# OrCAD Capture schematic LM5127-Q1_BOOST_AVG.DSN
size Custom; title: LM5127-Q1 2.2MHz Wide VIN Automotive Front-stage; rev: 1.0; note: Datasheet: NA     EVM: NA; note: Synchronous Step Down Converter
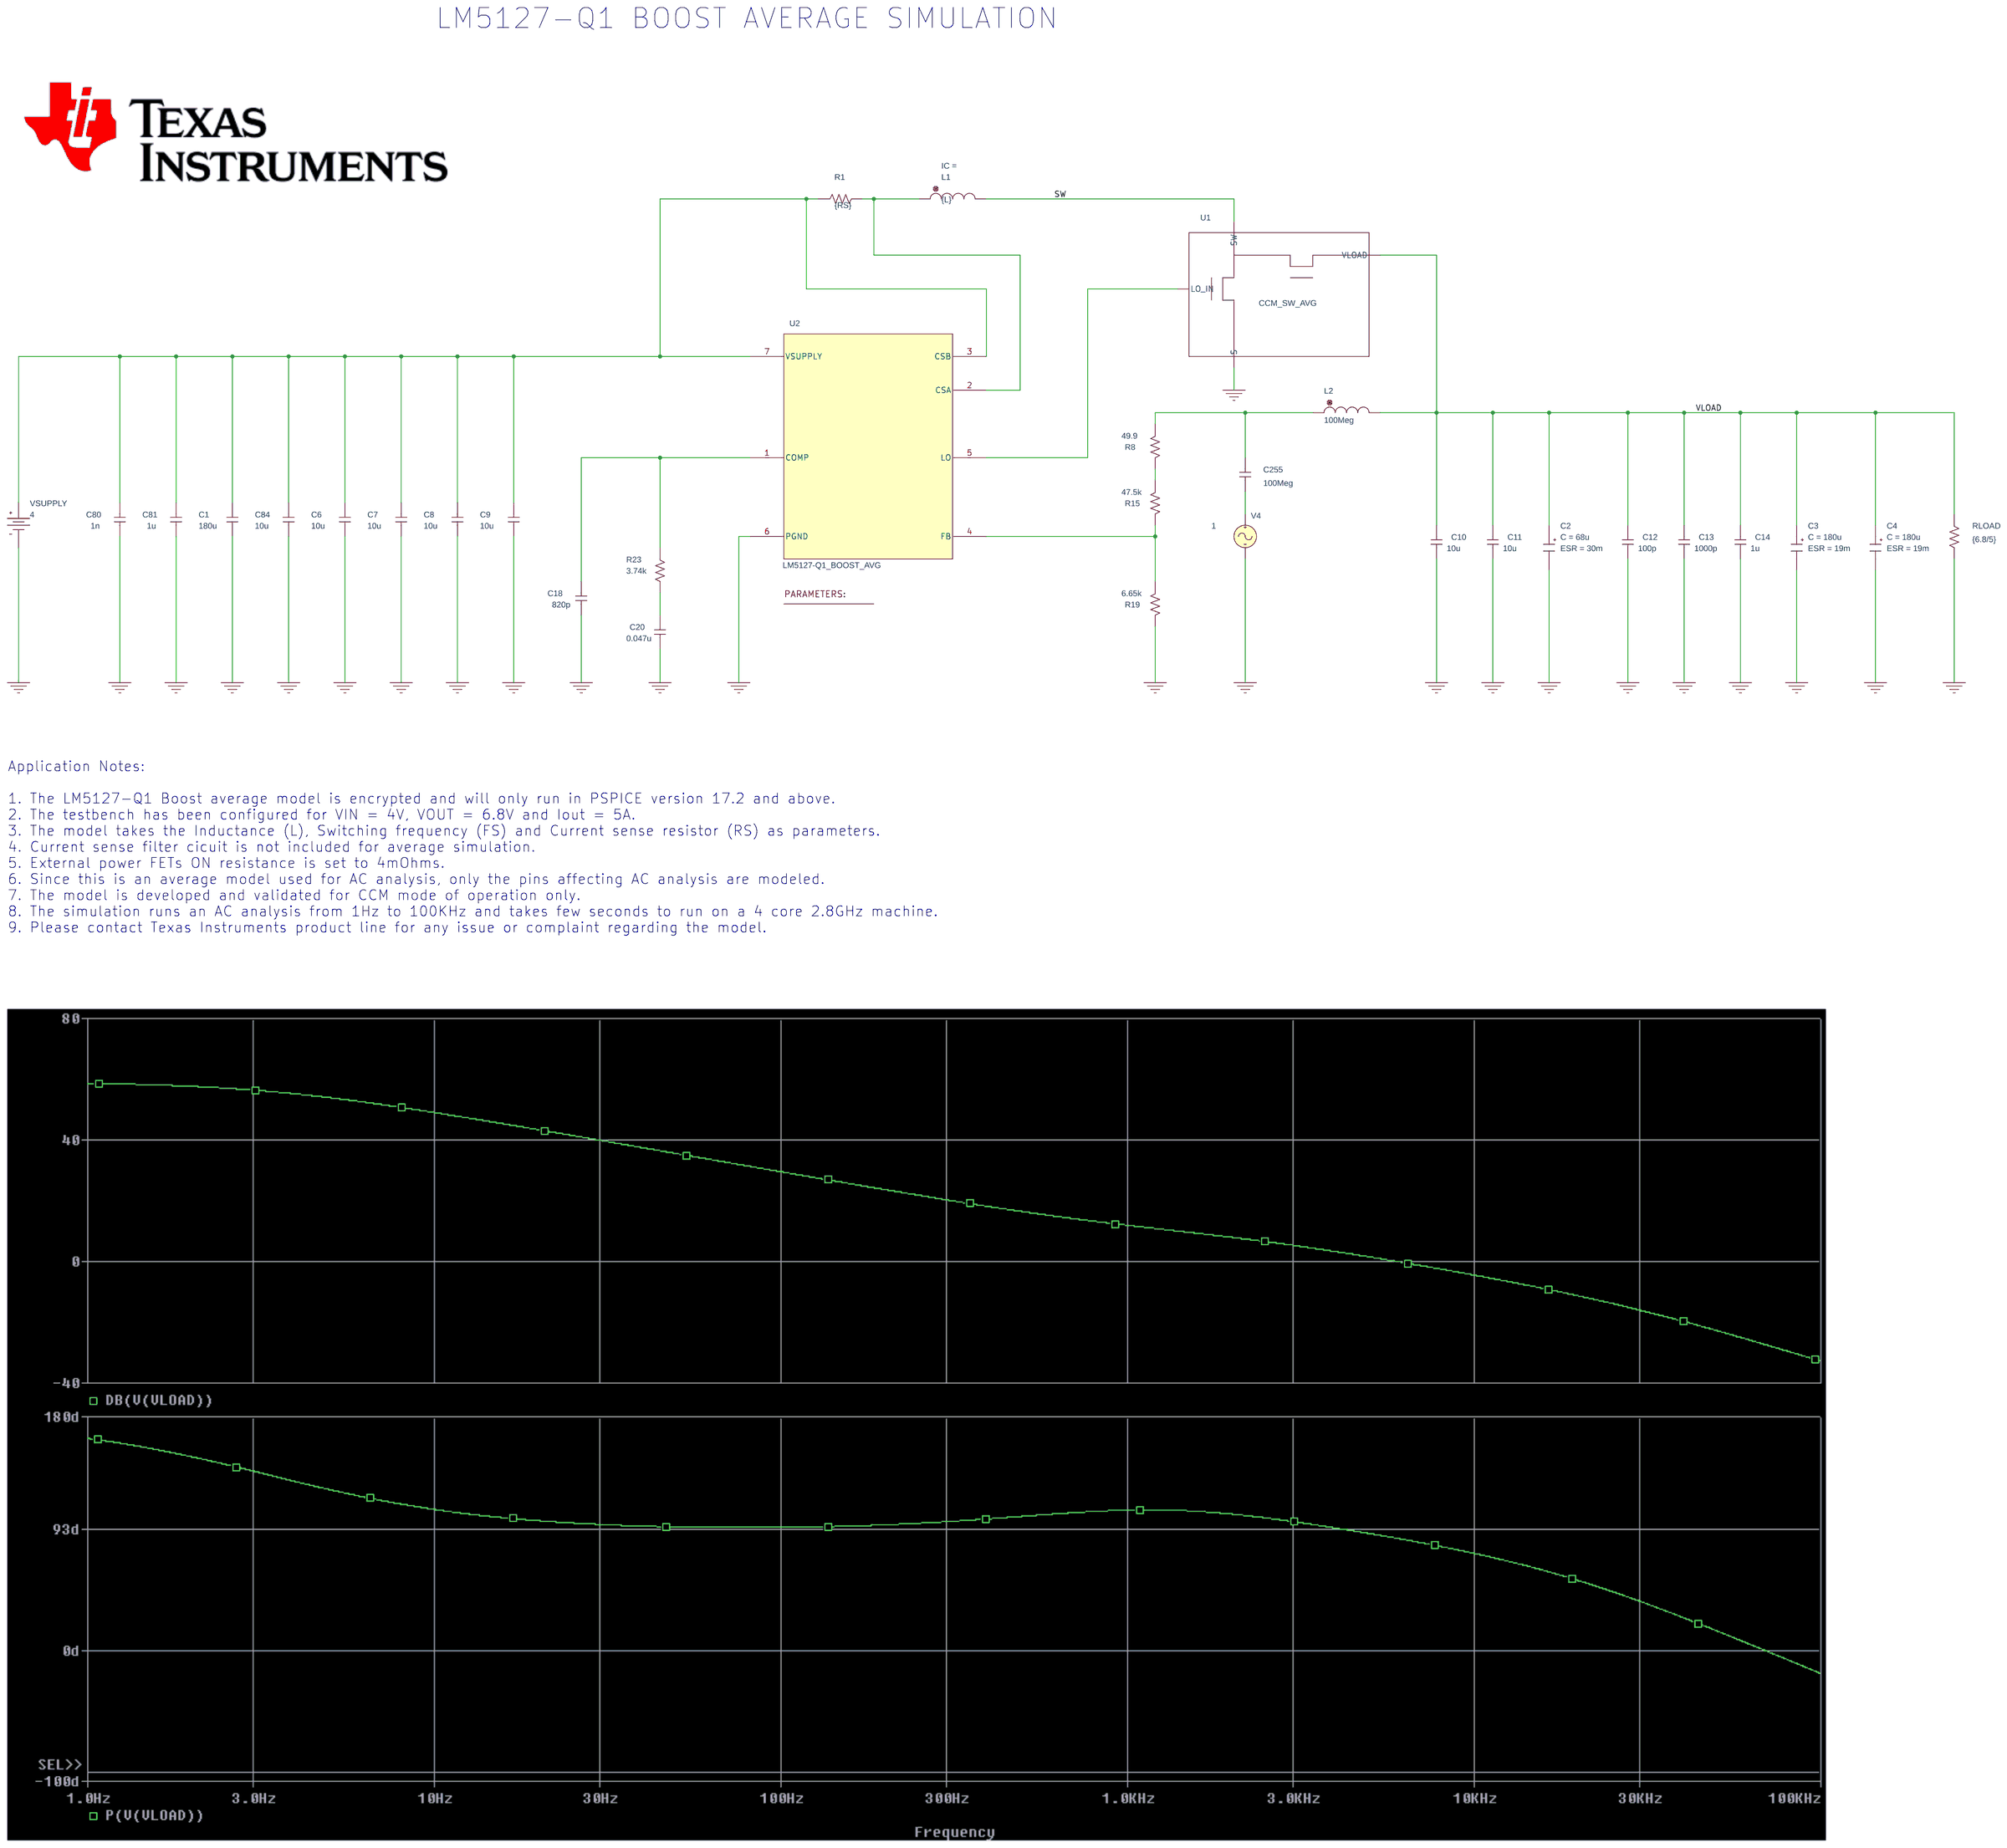
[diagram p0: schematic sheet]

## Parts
1  PARAM
C1  180u  [RAD/CK05]
C2  CESR
C3  CESR
C4  CESR
C6  10u  [RAD/CK05]
C7  10u  [RAD/CK05]
C8  10u  [RAD/CK05]
C9  10u  [RAD/CK05]
C10  10u  [RAD/CK05]
C11  10u  [RAD/CK05]
C12  100p  [RAD/CK05]
C13  1000p  [RAD/CK05]
C14  1u  [RAD/CK05]
C18  820p  [RAD/CK05]
C20  0.047u  [RAD/CK05]
C80  1n  [RAD/CK05]
C81  1u  [RAD/CK05]
C84  10u  [RAD/CK05]
C255  100Meg  [RAD/CK05]
L1  {L}  [DISC/.350x.175/LS.200x.100/.034]
L2  100Meg  [DISC/.350x.175/LS.200x.100/.034]
R1  {RS}  [AX/RC05]
R8  49.9  [AX/RC05]
R15  47.5k  [AX/RC05]
R19  6.65k  [AX/RC05]
R23  3.74k  [AX/RC05]
RLOAD  {6.8/5}  [AX/RC05]
U1  CCM_SW_AVG  [DRB0008A]
U2  LM5127-Q1_BOOST_AVG
V4  VAC
VSUPPLY  VDC

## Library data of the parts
1 = PARAM: FS: 440k; L: 470n; RS: 1.5m
C1 C6-C14 C18 C20 C80 C81 C84 C255 = C
C2 = CESR_0: C: 68u; ESR: 30m; PSpiceTemplate: X^@REFDES %IN %OUT @MODEL PARAMS:  ?C|C=@C||C=100u|  ?ESR|ESR=@ESR||ESR=0.01|; X: 1
C3 C4 = CESR_0: C: 180u; ESR: 19m; PSpiceTemplate: X^@REFDES %IN %OUT @MODEL PARAMS:  ?C|C=@C||C=100u|  ?ESR|ESR=@ESR||ESR=0.01|; X: 1
L1 L2 = L
R1 R8 R15 R19 R23 RLOAD = R
U1 = CCM_SW_AVG
U2 = LM5127-Q1_BOOST_AVG
V4 = VAC: ACMAG: 1; ACPHASE: 0
VSUPPLY = VDC: DC: 4

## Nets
0: C1.2 C2.2(OUT) C3.2(OUT) C4.2(OUT) C6.2 C7.2 C8.2 C9.2 C10.2 C11.2 C12.2 C13.2 C14.2 C18.2 C20.2 C80.2 C81.2 C84.2 R19.2 RLOAD.2 U1.S U2.6(PGND) V4.2(-) VSUPPLY.1(-)
SW: L1.2 U1.SW
VLOAD: C2.1(IN) C3.1(IN) C4.1(IN) C10.1 C11.1 C12.1 C13.1 C14.1 L2.2 RLOAD.1 U1.VLOAD
N299689: C255.2 V4.1(+)
N303301: C255.1 L2.1 R8.1
N303718: C1.1 C6.1 C7.1 C8.1 C9.1 C80.1 C81.1 C84.1 R1.1 U2.3(CSB) U2.7(VSUPPLY) VSUPPLY.0(+)
N303849: L1.1 R1.2 U2.2(CSA)
N305887: U1.LO_IN U2.5(LO)
N307172: C20.1 R23.2
N311691: R8.2 R15.1
N16777219: R15.2 R19.1 U2.4(FB)
N16785231: C18.1 R23.1 U2.1(COMP)

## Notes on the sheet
- LM5127-Q1 BOOST AVERAGE SIMULATION
- Application Notes:
  1. The LM5127-Q1 Boost average model is encrypted and will only run in PSPICE version 17.2 and above.
  2. The testbench has been configured for VIN = 4V, VOUT = 6.8V and Iout = 5A.
  3. The model takes the Inductance (L), Switching frequency (FS) and Current sense resistor (RS) as parameters.
  4. Current sense filter cicuit is not included for average simulation.
  5. External power FETs ON resistance is set to 4mOhms.
  6. Since this is an average model used for AC analysis, only the pins affecting AC analysis are modeled.
  7. The model is developed and validated for CCM mode of operation only.
  8. The simulation runs an AC analysis from 1Hz to 100KHz and takes few seconds to run on a 4 core 2.8GHz machine.
  9. Please contact Texas Instruments product line for any issue or complaint regarding the model.
